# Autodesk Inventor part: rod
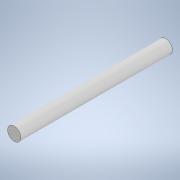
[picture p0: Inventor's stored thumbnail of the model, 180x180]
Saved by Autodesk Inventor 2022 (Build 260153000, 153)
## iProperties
Created: 2021-07
Part Number: rod
Material: Generic
Document SubType Name: Modeling
Designer: Chimms
Density: 1 g/cm^3
Appearance: Default
Author: Chimms
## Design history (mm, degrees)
sketch "Sketch1"
  geometry: C1 r 2 at (0, 0); 1 further point
  constraints: 1 centre point, 1 coincident
  dimensions: "d0" = 4 diameter of C1
extrude "Extrusion1" new body sketch "Sketch1" distance "d1" = 46; taper "d2" = 0 deg
sketch "Sketch2"
  geometry: C1 r 2 at (0, 0) reference; C2 r 2 at (0, 0); 1 further point
  constraints: 1 centre point, 1 coincident
extrude "Extrusion2" join sketch "Sketch2" distance "d3" = 7; taper "d4" = 0 deg
sketch "Sketch3"
  geometry: C1 r 2 at (0, 0); 1 further point
  constraints: 1 centre point, 1 coincident
  dimensions: "d5" = 4 diameter of C1
extrude "Extrusion3" cut sketch "Sketch3" distance "d6" = 10.5; taper "d7" = 0 deg
sketch "Sketch4"
  geometry: C1 r 2 at (0, 0); 1 further point
  constraints: 1 centre point, 1 coincident
  dimensions: "d8" = 4 diameter of C1
extrude "Extrusion4" join sketch "Sketch4" distance "d9" = 9.75; taper "d10" = 0 deg
sketch "Sketch5"
  geometry: C1 r 2 at (0, 0); 1 further point
  constraints: 1 centre point, 1 coincident
  dimensions: "d11" = 4 diameter of C1
extrude "Extrusion5" cut sketch "Sketch5" distance "d12" = 6.25; taper "d13" = 0 deg
body "Solid1"
